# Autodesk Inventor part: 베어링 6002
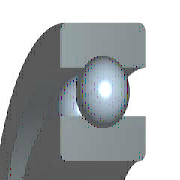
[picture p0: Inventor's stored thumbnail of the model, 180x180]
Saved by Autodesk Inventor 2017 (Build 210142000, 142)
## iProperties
IsCustomPart: 0
Created: 2012-02
Part Number: 베어링 6002
Material: 강철, 연강
Description: 깊은 그루브 볼 베어링
Document SubType Name: Modeling
Standard: KS B 2023
Designer: mduedu
Standards Organization: KS
Language: ko-KR
Size Designation: 6002 - 15 x 32 x 9
Categories: <MemberInstance><Categories><Category DisplayName="샤프트 부품" InternalName="7f7aeb1f-a693-4053-b835-cee3144e0d98" Mnemonic="SHFT"><Category DisplayName="베어링" Inter
Density: 1 g/cm^3
Appearance: 노란색
Author: mduedu
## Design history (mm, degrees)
sketch "스케치" dims "d0" = 4.42 (= -0.26 x WD + 0.26 x BD)
  geometry: L1 (2.29, 11.75)-(6.71, 11.75); L2 (4.5, 11.75)-(4.5, 9.54); L3 (4.5, 11.75)-(4.5, 13.96); L4 (2.858, 10.271)-(0, 10.271); L5 (0, 7.5)-(9, 7.5); L6 (2.858, 13.229)-(0, 13.229); L7 (0, 16)-(9, 16); L8 (9, 7.5)-(9, 10.271); L9 (6.142, 10.271)-(9, 10.271); L10 (6.142, 13.229)-(9, 13.229); L11 (9, 16)-(9, 13.229); L12 (-1.4, 0)-(8.4, 0) reference; L13 (0, -0.3)-(0, 5.3) reference
  constraints: 22 end point, 4 point on line, 2 collinear, 2 perpendicular, 2 symmetric about line, 1 midpoint, 1 parallel, 14 other
  dimensions: "d9" = 15 diameter of L5 L12 (= WD); "d11" = 32 diameter of L7 L12 (= BD); "d12" = 9 distance between parallel lines of L8 L13 (= KB); "d13" = 20.542 diameter of L9 L12 (= 0.326 x BD + 0.674 x WD)
revolve "본체" stored, may be unused: angle "d6" = 90 deg
revolve "볼" stored, may be unused: angle "d7" = 90 deg
pattern_circular "IDS_ARRAYBALL[SIMPL:T]" dims angle "d3" = 360 deg
body "Solid1"
fillet "모깎기1" dims "d1" = 0.3 (= KRS)
other parameters: "WD" = 15 [user parameter; used in 5 equation terms], "BD" = 32 [user parameter; used in 5 equation terms], "KB" = 9 [user parameter; used in 1 equation term], "KRS" = 0.3 [user parameter; used in 1 equation term], "d4" = 0, "d5" = 0, "d8" = 0, "d14" = 0, "d15" = 0, "BBA" = 0 [user parameter], "BC0" = 2850000 [user parameter], "BC" = 5590000 [user parameter], "BR" = 16 (= 0.5 x BD) [user parameter], "WR" = 7.5 (= 0.5 x WD) [user parameter]
